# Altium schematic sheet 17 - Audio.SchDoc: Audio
size A3; PageSetup: Record=PageOptions¦CenterHorizontal=True¦CenterVertical=True¦PrintScale=0.70¦XCorrection=1.00¦YCorrection=1.00¦PrintKind=0¦BorderSize=5000000¦LeftOffset=0¦BottomOffset=0¦Orientation=2¦PaperLength=4200¦PaperWidth=2970¦Scale=100¦PaperSource=7¦PrintQuality=600¦MediaType=1¦DitherType=10¦PaperKind=A4¦PrintScaleMode=1; Author: Juan Anzola; SheetNumber: 17; SheetTotal: 21
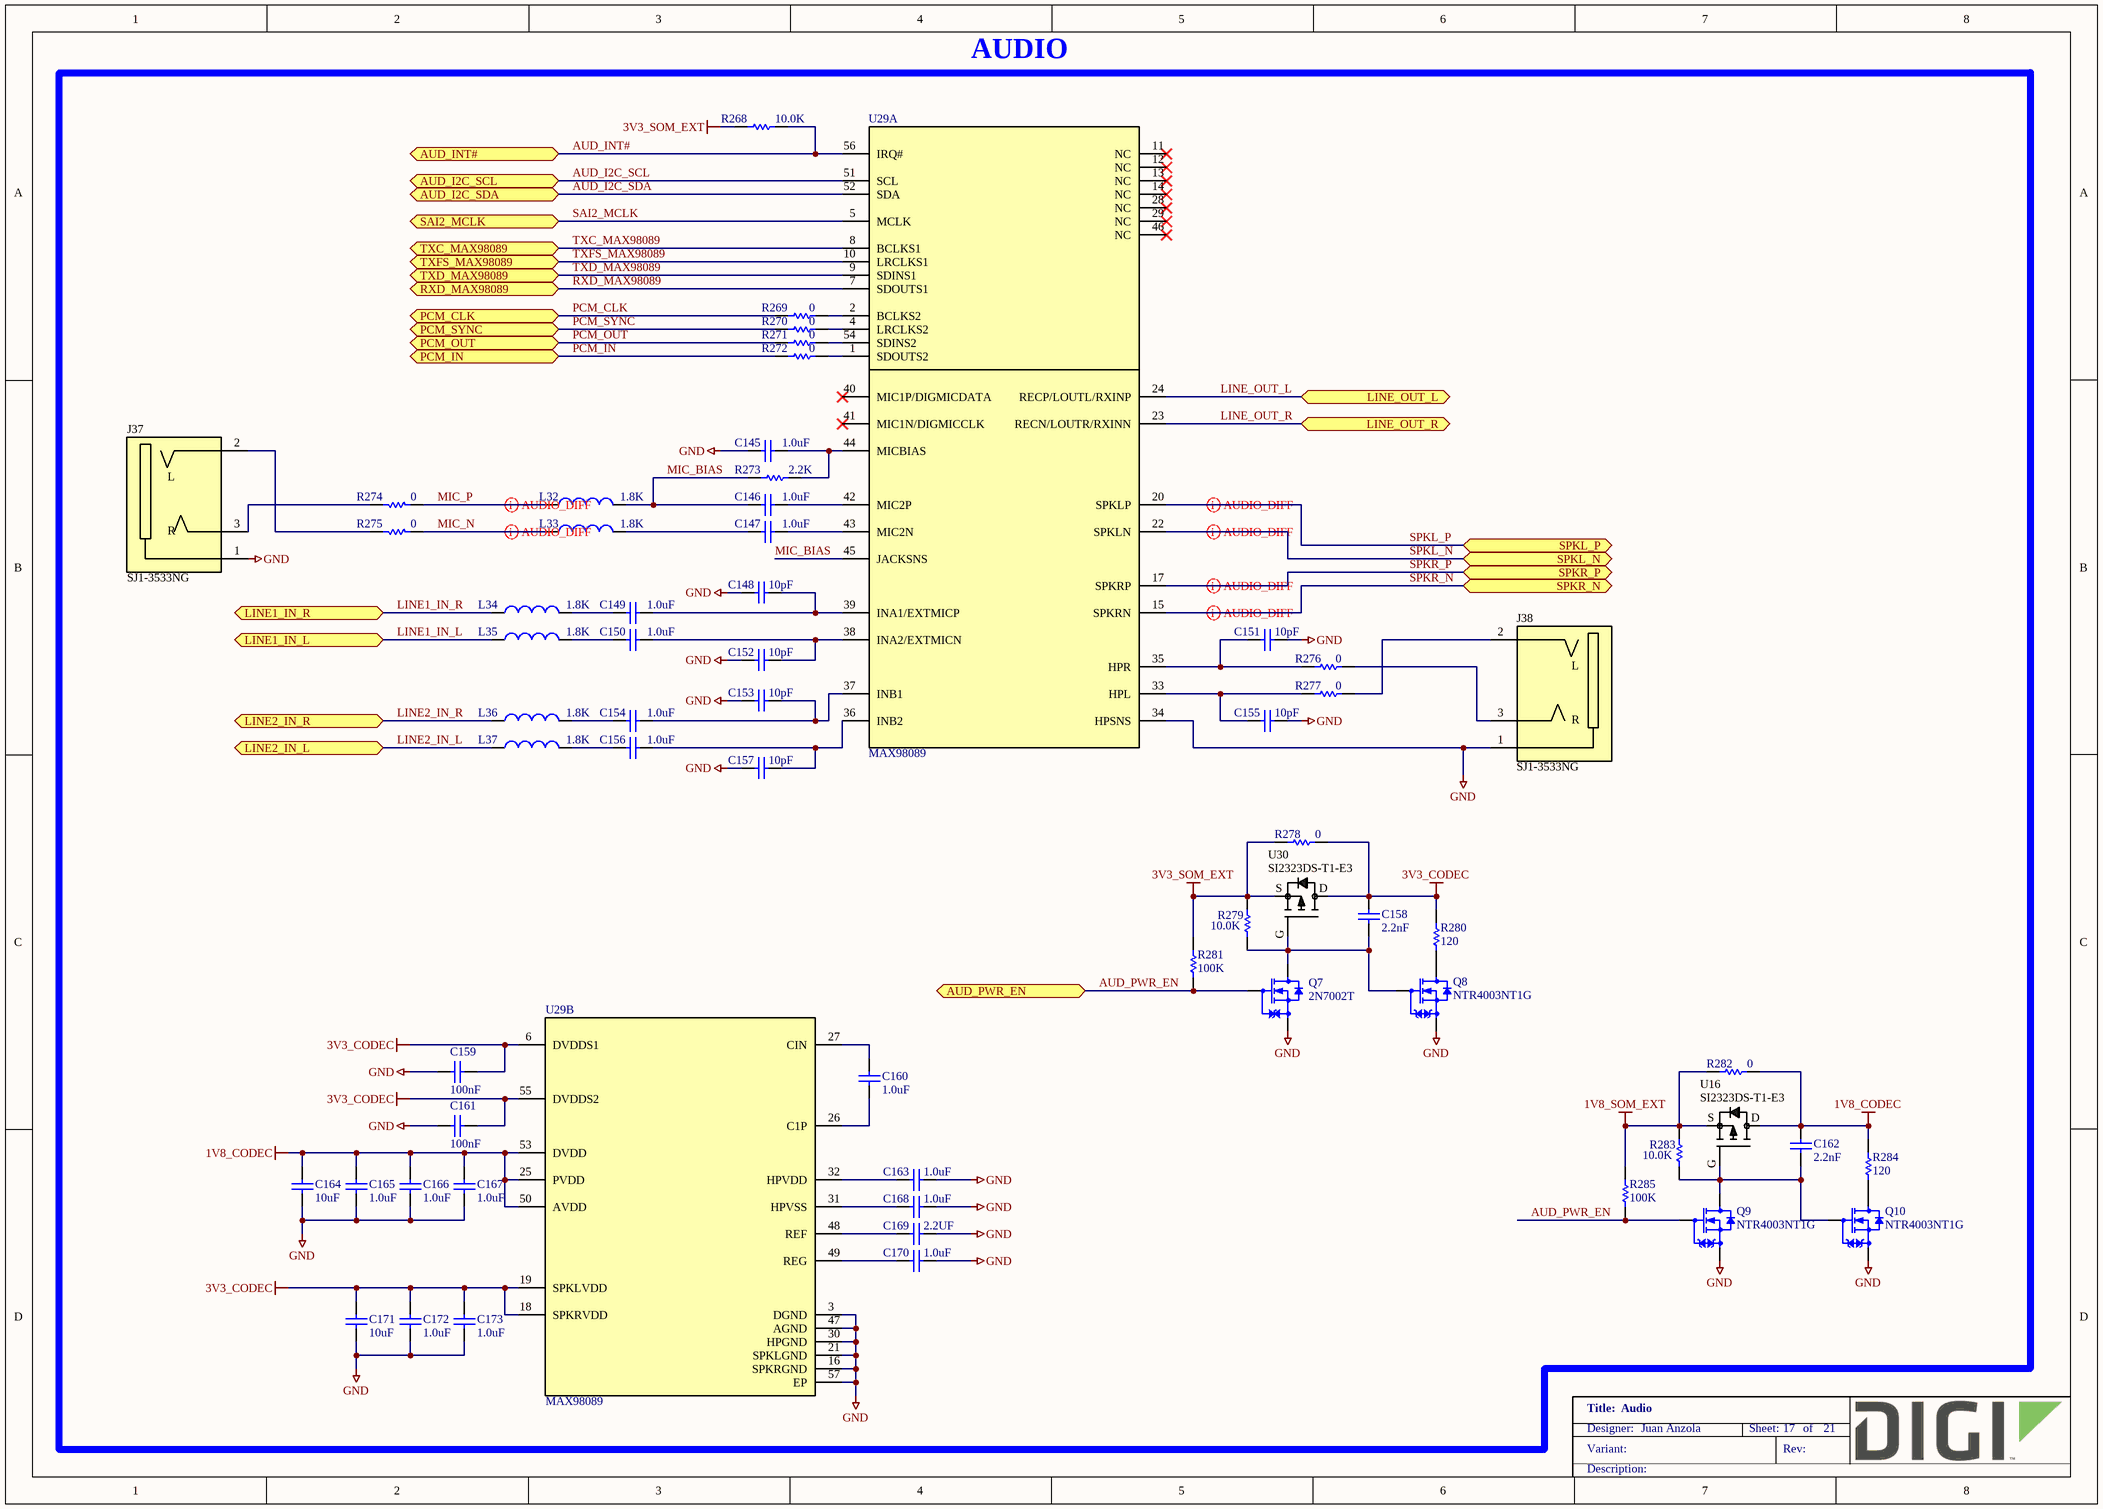
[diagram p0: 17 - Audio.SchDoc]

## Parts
C145  1.0uF  [CAPC1005X55N]
C146  1.0uF  [CAPC1005X55N]
C147  1.0uF  [CAPC1005X55N]
C148  10pF  [CAPC1005X55N]
C149  1.0uF  [CAPC1005X55N]
C150  1.0uF  [CAPC1005X55N]
C151  10pF  [CAPC1005X55N]
C152  10pF  [CAPC1005X55N]
C153  10pF  [CAPC1005X55N]
C154  1.0uF  [CAPC1005X55N]
C155  10pF  [CAPC1005X55N]
C156  1.0uF  [CAPC1005X55N]
C157  10pF  [CAPC1005X55N]
C158  2.2nF  [CAPC1608X90N]
C159  100nF  [CAPC1005X55N]
C160  1.0uF  [CAPC1005X55N]
C161  100nF  [CAPC1005X55N]
C162  2.2nF  [CAPC1608X90N]
C163  1.0uF  [CAPC1005X55N]
C164  10uF  [CAPC1005X55N]
C165  1.0uF  [CAPC1005X55N]
C166  1.0uF  [CAPC1005X55N]
C167  1.0uF  [CAPC1005X55N]
C168  1.0uF  [CAPC1005X55N]
C169  2.2UF  [CAPC1608X90N]
C170  1.0uF  [CAPC1005X55N]
C171  10uF  [CAPC1005X55N]
C172  1.0uF  [CAPC1005X55N]
C173  1.0uF  [CAPC1005X55N]
J37  SJ1-3533NG  [CUI_SJ1-3533N]
J38  SJ1-3533NG  [CUI_SJ1-3533N]
L32  1.8K  [INDC1005X60N]
L33  1.8K  [INDC1005X60N]
L34  1.8K  [INDC1005X60N]
L35  1.8K  [INDC1005X60N]
L36  1.8K  [INDC1005X60N]
L37  1.8K  [INDC1005X60N]
Q7  2N7002T  [SOTFL50P160X80_GSD-3N]
Q8  NTR4003NT1G  [SOT95P240X110_GSD-3N]
Q9  NTR4003NT1G  [SOT95P240X110_GSD-3N]
Q10  NTR4003NT1G  [SOT95P240X110_GSD-3N]
R268  10.0K  [RESC1005X40N]
R269  0  [RESC1005X40N]
R270  0  [RESC1005X40N]
R271  0  [RESC1005X40N]
R272  0  [RESC1005X40N]
R273  2.2K  [RESC1005X40N]
R274  0  [RESC1005X40N]
R275  0  [RESC1005X40N]
R276  0  [RESC1005X40N]
R277  0  [RESC1005X40N]
R278  0  [RESC1609X55N]
R279  10.0K  [RESC1005X40N]
R280  120  [RESC1005X40N]
R281  100K  [RESC1005X40N]
R282  0  [RESC1609X55N]
R283  10.0K  [RESC1005X40N]
R284  120  [RESC1005X40N]
R285  100K  [RESC1005X40N]
U16  SI2323DS-T1-E3  [SOT95P240X110_GSD-3N]
U29  MAX98089  [QFN40P700X700X80-57T560X560N]  (parts A,B of 2)
U30  SI2323DS-T1-E3  [SOT95P240X110_GSD-3N]

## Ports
AUD_I2C_SCL (bidir), AUD_I2C_SDA (bidir), AUD_INT# (bidir), AUD_PWR_EN (bidir), LINE1_IN_L (bidir), LINE1_IN_R (bidir), LINE2_IN_L (bidir), LINE2_IN_R (bidir), LINE_OUT_L (bidir), LINE_OUT_R (bidir), PCM_CLK (bidir), PCM_IN (bidir), PCM_OUT (bidir), PCM_SYNC (bidir), RXD_MAX98089 (bidir), SAI2_MCLK (bidir), SPKL_N (bidir), SPKL_P (bidir), SPKR_N (bidir), SPKR_P (bidir), TXC_MAX98089 (bidir), TXD_MAX98089 (bidir), TXFS_MAX98089 (bidir)

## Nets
1V8_CODEC: C162.2 C164.2 C165.1 C166.1 C167.1 R282.2 R284.1 U16.D U29.25(PVDD) U29.50(AVDD) U29.53(DVDD)
1V8_SOM_EXT: R282.1 R283.1 R285.1 U16.S
3V3_CODEC: C158.2 C159.2 C161.2 C171.2 C172.1 C173.1 R278.2 R280.1 U29.6(DVDDS1) U29.18(SPKRVDD) U29.19(SPKLVDD) U29.55(DVDDS2) U30.D
3V3_SOM_EXT: R268.1 R278.1 R279.1 R281.1 U30.S
GND: C145.2 C148.2 C151.2 C152.2 C153.2 C155.2 C157.2 C159.1 C161.1 C163.1 C164.1 C165.2 C166.2 C167.2 C168.1 C169.1 C170.1 C171.1 C172.2 C173.2 J37.1 J38.1 Q7.S Q8.S Q9.S Q10.S U29.3(DGND) U29.16(SPKRGND) U29.21(SPKLGND) U29.30(HPGND) U29.34(HPSNS) U29.47(AGND) U29.57(EP)
AUD_I2C_SCL: U29.51(SCL) ; port AUD_I2C_SCL
AUD_I2C_SDA: U29.52(SDA) ; port AUD_I2C_SDA
AUD_INT#: R268.2 U29.56(IRQ#) ; port AUD_INT#
AUD_PWR_EN: Q7.G Q9.G R281.2 R285.2 ; port AUD_PWR_EN
LINE1_IN_L: L35.1 ; port LINE1_IN_L
LINE1_IN_R: L34.1 ; port LINE1_IN_R
LINE2_IN_L: L37.1 ; port LINE2_IN_L
LINE2_IN_R: L36.1 ; port LINE2_IN_R
LINE_OUT_L: U29.24(RECP/LOUTL/RXINP) ; port LINE_OUT_L
LINE_OUT_R: U29.23(RECN/LOUTR/RXINN) ; port LINE_OUT_R
MIC_BIAS: C146.2 L32.2 R273.1 U29.45(JACKSNS)
MIC_N: L33.1 R275.1
MIC_P: L32.1 R274.1
PCM_CLK: R269.1 ; port PCM_CLK
PCM_IN: R272.1 ; port PCM_IN
PCM_OUT: R271.1 ; port PCM_OUT
PCM_SYNC: R270.1 ; port PCM_SYNC
RXD_MAX98089: U29.7(SDOUTS1) ; port RXD_MAX98089
SAI2_MCLK: U29.5(MCLK) ; port SAI2_MCLK
SPKL_N: U29.22(SPKLN) ; port SPKL_N
SPKL_P: U29.20(SPKLP) ; port SPKL_P
SPKR_N: U29.15(SPKRN) ; port SPKR_N
SPKR_P: U29.17(SPKRP) ; port SPKR_P
TXC_MAX98089: U29.8(BCLKS1) ; port TXC_MAX98089
TXD_MAX98089: U29.9(SDINS1) ; port TXD_MAX98089
TXFS_MAX98089: U29.10(LRCLKS1) ; port TXFS_MAX98089
NetC145_1: C145.1 R273.2 U29.44(MICBIAS)
NetC146_1: C146.1 U29.42(MIC2P)
NetC147_1: C147.1 U29.43(MIC2N)
NetC147_2: C147.2 L33.2
NetC148_1: C148.1 C149.1 U29.39(INA1/EXTMICP)
NetC149_2: C149.2 L34.2
NetC150_1: C150.1 C152.1 U29.38(INA2/EXTMICN)
NetC150_2: C150.2 L35.2
NetC151_1: C151.1 R276.1 U29.35(HPR)
NetC153_1: C153.1 C154.1 U29.37(INB1)
NetC154_2: C154.2 L36.2
NetC155_1: C155.1 R277.1 U29.33(HPL)
NetC156_1: C156.1 C157.1 U29.36(INB2)
NetC156_2: C156.2 L37.2
NetC158_1: C158.1 Q7.D Q8.G R279.2 U30.G
NetC160_1: C160.1 U29.27(CIN)
NetC160_2: C160.2 U29.26(C1P)
NetC162_1: C162.1 Q9.D Q10.G R283.2 U16.G
NetC163_2: C163.2 U29.32(HPVDD)
NetC168_2: C168.2 U29.31(HPVSS)
NetC169_2: C169.2 U29.48(REF)
NetC170_2: C170.2 U29.49(REG)
NetJ37_2: J37.2 R275.2
NetJ37_3: J37.3 R274.2
NetJ38_2: J38.2 R277.2
NetJ38_3: J38.3 R276.2
NetQ8_D: Q8.D R280.2
NetQ10_D: Q10.D R284.2
NetR269_2: R269.2 U29.2(BCLKS2)
NetR270_2: R270.2 U29.4(LRCLKS2)
NetR271_2: R271.2 U29.54(SDINS2)
NetR272_2: R272.2 U29.1(SDOUTS2)

Not connected (* = marked no-connect by the designer): U29 11(NC)* 12(NC)* 13(NC)* 14(NC)* 28(NC)* 29(NC)* 40(MIC1P/DIGMICDATA)* 41(MIC1N/DIGMICCLK)* 46(NC)*

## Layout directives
differential pair: MIC_N, MIC_P, SPKL_N, SPKL_P, SPKR_N, SPKR_P

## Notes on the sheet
- AUDIO

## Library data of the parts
C145-C147 C149 C150 C154 C156 = 1000073: CAP CER 1UF 6.3V 20% X5R 0402; Part_Type: Capacitor; Manufacturer: Murata; Manufacturer_Part_Number: GRM155R60J105ME19D; Digi_PN: 14050543; Component_Life_Cycle_State: Proven; Area: 0.95; Project: Adjustable Foundation
C148 C151-C153 C155 C157 = 1001541: CAP CER 10PF 50V 5% NP0 0402; Part_Type: Capacitor; Manufacturer: Murata; Manufacturer_Part_Number: GRM1555C1H100JA01D; Note: 14050750 = Digi No. for GE WDNU; Digi_PN: 14050362; Component_Life_Cycle_State: Reviewed; Area: 0,95; Project: KITT v0.4; Tolerance: 5; Temp_Coef: C0G, NP0
C158 C162 = 1002727: CAP CER 2200PF 50V X7R 5% 0603; Part_Type: Capacitor; Manufacturer: Kemet; Manufacturer_Part_Number: C0603C222J5RACTU; Digi_PN: 14050443; Component_Life_Cycle_State: Pending; Area: 2,27
C159 C161 = 1000006: CAP 100nF 16V 10% X7R 0402; Part_Type: Capacitor; Manufacturer: Murata; Manufacturer_Part_Number: GRM155R71C104KA88D; Digi_PN: 14050552; Component_Life_Cycle_State: CAD Reviewed; Area: 0.95; Project: KITT; Tolerance: 10
C160 C163 C165-C168 C170 C172 C173 = 1001167: CAP CER 1UF 10V 10% X5R 0402; Part_Type: Capacitor; Manufacturer: Murata; Manufacturer_Part_Number: GRM155R61A105KE15D; Digi_PN: 14050399; Component_Life_Cycle_State: Reviewed; Area: 0.95; Project: CCWMX6_SBC board
C164 C171 = 1001168: CAP CER 10UF 10V 20% X5R 0402; Part_Type: Capacitor; Manufacturer: Samsung; Manufacturer_Part_Number: CL05A106MP5NUNC; Digi_PN: 14050689; Component_Life_Cycle_State: Reviewed; Area: 0.95; Project: CCWMX6_SBC board
C169 = 1001303: CAP CER 2.2UF 16V 10% X5R 0603; Part_Type: Capacitor; Manufacturer: TDK Corporation; Manufacturer_Part_Number: C1608X5R1C225K080AB; Digi_PN: 14050730; Component_Life_Cycle_State: Reviewed; Area: 2,27; Project: Pinnacle
J37 J38 = 1002596: CONN JACK STEREO 3.5MM R/A; Part_Type: Connector; Manufacturer: CUI Inc.; Digi_PN: 18000594; Component_Life_Cycle_State: Reviewed; Area: 163.02; Project: CCWMX6_SBC board
L32-L37 = 1002041: FERRITE BEAD 1.8 KOHM 0402 1LN; Manufacturer: Murata; Manufacturer_Part_Number: BLM15HD182SN1D; Digi_PN: 21000461; Component_Life_Cycle_State: Reviewed; Area: 2.2; Project: iMX6UL+PMIC
Q7 = 1000715: MOSFET N-CH 60V 115MA SOT-523F; Part_Type: Transistor; Manufacturer: Fairchild Semiconductor; Digi_PN: 17050797; Component_Life_Cycle_State: CAD Reviewed; Area: 3.06; Project: SmartMeter2; Note: 17050841 = Digi No. for GE WDNU
Q8-Q10 = 1000306: MOSFET N-CH 30V 500MA SOT-23; Part_Type: Transistor; Manufacturer: On Semiconductor; Digi_PN: 17050809; Component_Life_Cycle_State: Proven; Area: 10,92; Project: Adjustable Foundation
R268 R279 R283 = 1000537: RES 10.0K OHM 1/10W 1% 0402 SMD; Part_Type: Resistor; Manufacturer: Panasonic - ECG; Manufacturer_Part_Number: ERJ-2RKF1002X; Component_Life_Cycle_State: CAD Reviewed; Area: 0.95; Project: KITT; Power_WV_SRF: 100; Digi_PN: 13051084
R269-R272 R274-R277 = 1000076: RES 0.0 OHM 1/10W 0402 SMD; Part_Type: Resistor; Manufacturer: Panasonic - ECG; Manufacturer_Part_Number: ERJ-2GE0R00X; Component_Life_Cycle_State: Proven; Area: 0.95; Project: Adjustable Foundation; Power_WV_SRF: 10; Digi_PN: 13050387
R273 = 1001156: RES 2.20K OHM 1/16W 1% 0402 SMD; Part_Type: Resistor; Manufacturer: Yageo; Manufacturer_Part_Number: RC0402FR-072K2L; Note: 13051099 = Digi No. for GE WDNU; Digi_PN: 13050699; Component_Life_Cycle_State: Reviewed; Area: 0,95; Project: CCWMX6_SBC board
R278 R282 = 1000208: RES 0.0 OHM 1/10W 0603; Part_Type: Resistor; Manufacturer: Panasonic - ECG; Manufacturer_Part_Number: ERJ-3GEY0R00V; Note: 13051103 = Digi No. for GE WDNU; Digi_PN: 13050568; Component_Life_Cycle_State: Reviewed; Area: 2.5; Project: Adjustable Foundation; Voltage: 75V
R280 R284 = 1001158: RES 120 OHM 1/16W 1% 0402 SMD; Part_Type: Resistor; Manufacturer: Yageo; Manufacturer_Part_Number: RC0402FR-07120RL; Digi_PN: 13050832; Component_Life_Cycle_State: Reviewed; Area: 0.95; Project: CCWMX6_SBC board; Note: 13051102 = Digi No. for GE WDNU
R281 R285 = 1000480: RES 100K OHM 1/10W 1% 0402 SMD; Part_Type: Resistor; Manufacturer: Panasonic - ECG; Manufacturer_Part_Number: ERJ-2RKF1003X; Digi_PN: 13051063; Component_Life_Cycle_State: CAD Reviewed; Area: 0.95; Project: KITT; Power_WV_SRF: 100
U16 U30 = 1001163: MOSFET P-CH 20V 3.7A SOT23-3; Part_Type: IC; Manufacturer: Vishay Siliconix; Digi_PN: 17050358; Component_Life_Cycle_State: Reviewed; Area: 10.92; Project: CCWMX6_SBC board
U29 = 1002001: IC CODEC AUDIO FLEXSOUND 56TQFN; Manufacturer: Maxim; Manufacturer_Part_Number: MAX98089ETN+T; Component_Life_Cycle_State: Reviewed; Area: 49; Project: iMX6UL+PMIC; Digi_PN: 16052036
